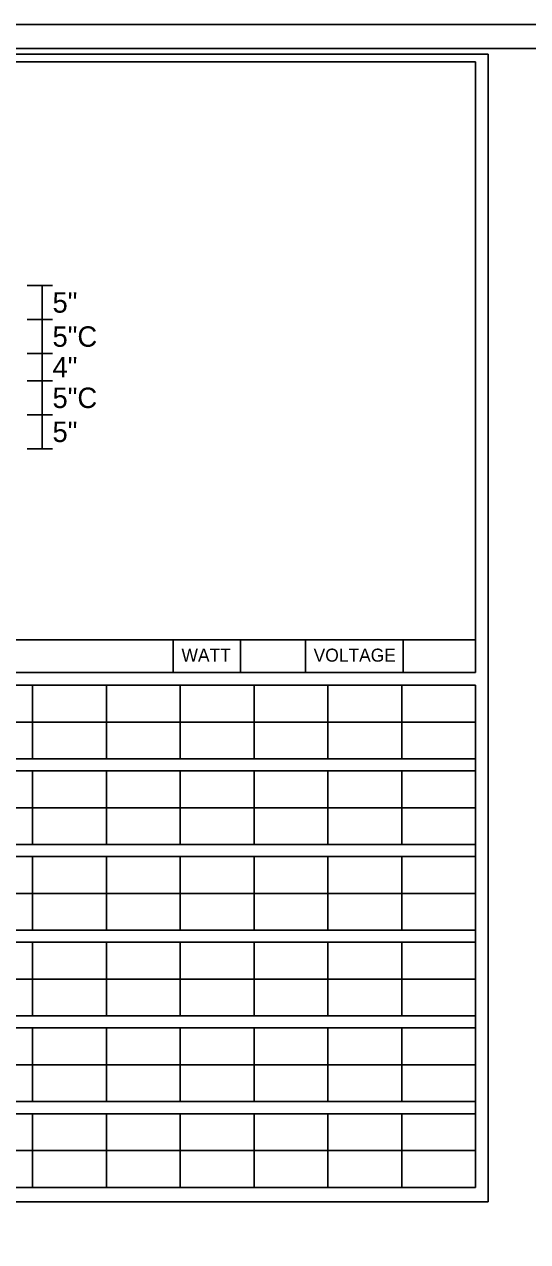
# Model space of a CAD drawing. Extents: x 17890587 to 17890754, y 17897693 to 17897992.
# Drawn here: x 17890605.35 to 17890611.5, y 17897889.3 to 17897904.2 of the extents above; entities that cross this region are included whole.
import ezdxf

# ---------------------------------------------------------------- set-up
doc = ezdxf.new("R2010")
doc.units = 0
for name, color, linetype in [('GSDims', 7, 'Continuous'), ('PlotBorder_dp', 7, 'Continuous'), ('SheetBorder_dp', 7, 'Continuous'), ('SheetLinesMisc2_dp', 7, 'Continuous'), ('TextMinor', 7, 'Continuous')]:
    doc.layers.add(name, color=color, linetype=linetype)

msp = doc.modelspace()

# ---------------------------------------------------------------- linework, layer by layer
at = {"layer": 'GSDims'}
for p, q in [((17890605.379, 17897901.007), (17890605.691, 17897901.007)), ((17890605.566, 17897900.591), (17890605.566, 17897901.007)), ((17890605.379, 17897900.591), (17890605.691, 17897900.591)), ((17890605.379, 17897900.591), (17890605.691, 17897900.591)), ((17890605.566, 17897900.591), (17890605.566, 17897900.174)), ((17890605.379, 17897900.174), (17890605.691, 17897900.174)), ((17890605.379, 17897900.174), (17890605.691, 17897900.174)), ((17890605.566, 17897899.841), (17890605.566, 17897900.174)), ((17890605.379, 17897899.841), (17890605.691, 17897899.841)), ((17890605.379, 17897899.841), (17890605.691, 17897899.841)), ((17890605.566, 17897899.841), (17890605.566, 17897899.424)), ((17890605.379, 17897899.424), (17890605.691, 17897899.424)), ((17890605.379, 17897899.424), (17890605.691, 17897899.424)), ((17890605.566, 17897899.007), (17890605.566, 17897899.424)), ((17890605.379, 17897899.007), (17890605.691, 17897899.007))]:
    msp.add_line(p, q, dxfattribs=at)
at = {"layer": 'PlotBorder_dp'}
msp.add_lwpolyline([(17890586.756, 17897873.104), (17890635.165, 17897873.104), (17890635.165, 17897904.203), (17890586.756, 17897904.203)], close=True, dxfattribs=at)
at = {"layer": 'SheetBorder_dp'}
msp.add_line((17890588.37, 17897903.909), (17890633.551, 17897903.909), dxfattribs=at)
at = {"layer": 'SheetLinesMisc2_dp'}
for p, q in [((17890588.454, 17897903.839), (17890611.019, 17897903.839)), ((17890611.019, 17897903.839), (17890611.019, 17897889.792)), ((17890595.516, 17897903.746), (17890610.866, 17897903.746)), ((17890610.866, 17897896.269), (17890610.866, 17897903.746)), ((17890595.516, 17897896.67), (17890610.866, 17897896.67)), ((17890607.167, 17897896.67), (17890607.167, 17897896.269)), ((17890607.99, 17897896.67), (17890607.99, 17897896.269)), ((17890608.784, 17897896.67), (17890608.784, 17897896.269)), ((17890609.98, 17897896.67), (17890609.98, 17897896.269)), ((17890595.516, 17897896.269), (17890610.866, 17897896.269)), ((17890588.67, 17897896.115), (17890610.866, 17897896.115)), ((17890605.448, 17897896.115), (17890605.448, 17897895.213)), ((17890606.351, 17897896.115), (17890606.351, 17897895.213)), ((17890607.254, 17897896.115), (17890607.254, 17897895.213)), ((17890608.157, 17897896.115), (17890608.157, 17897895.213)), ((17890609.06, 17897896.115), (17890609.06, 17897895.213)), ((17890609.963, 17897896.115), (17890609.963, 17897895.213)), ((17890610.866, 17897889.969), (17890610.866, 17897896.115)), ((17890588.67, 17897895.664), (17890610.866, 17897895.664)), ((17890588.67, 17897895.213), (17890610.866, 17897895.213)), ((17890588.67, 17897895.066), (17890610.866, 17897895.066)), ((17890605.448, 17897895.066), (17890605.448, 17897894.164)), ((17890606.351, 17897895.066), (17890606.351, 17897894.164)), ((17890607.254, 17897895.066), (17890607.254, 17897894.164)), ((17890608.157, 17897895.066), (17890608.157, 17897894.164)), ((17890609.06, 17897895.066), (17890609.06, 17897894.164)), ((17890609.963, 17897895.066), (17890609.963, 17897894.164)), ((17890588.67, 17897894.615), (17890610.866, 17897894.615)), ((17890588.67, 17897894.164), (17890610.866, 17897894.164)), ((17890588.67, 17897894.017), (17890610.866, 17897894.017)), ((17890605.448, 17897894.017), (17890605.448, 17897893.116)), ((17890606.351, 17897894.017), (17890606.351, 17897893.116)), ((17890607.254, 17897894.017), (17890607.254, 17897893.116)), ((17890608.157, 17897894.017), (17890608.157, 17897893.116)), ((17890609.06, 17897894.017), (17890609.06, 17897893.116)), ((17890609.963, 17897894.017), (17890609.963, 17897893.116)), ((17890588.67, 17897893.566), (17890610.866, 17897893.566)), ((17890588.67, 17897893.116), (17890610.866, 17897893.116)), ((17890588.67, 17897892.969), (17890610.866, 17897892.969)), ((17890605.448, 17897892.969), (17890605.448, 17897892.067)), ((17890606.351, 17897892.969), (17890606.351, 17897892.067)), ((17890607.254, 17897892.969), (17890607.254, 17897892.067)), ((17890608.157, 17897892.969), (17890608.157, 17897892.067)), ((17890609.06, 17897892.969), (17890609.06, 17897892.067)), ((17890609.963, 17897892.969), (17890609.963, 17897892.067)), ((17890588.67, 17897892.518), (17890610.866, 17897892.518)), ((17890588.67, 17897892.067), (17890610.866, 17897892.067)), ((17890588.67, 17897891.92), (17890610.866, 17897891.92)), ((17890605.448, 17897891.92), (17890605.448, 17897891.018)), ((17890606.351, 17897891.92), (17890606.351, 17897891.018)), ((17890607.254, 17897891.92), (17890607.254, 17897891.018)), ((17890608.157, 17897891.92), (17890608.157, 17897891.018)), ((17890609.06, 17897891.92), (17890609.06, 17897891.018)), ((17890609.963, 17897891.92), (17890609.963, 17897891.018)), ((17890588.67, 17897891.469), (17890610.866, 17897891.469)), ((17890588.67, 17897891.018), (17890610.866, 17897891.018)), ((17890588.67, 17897890.871), (17890610.866, 17897890.871)), ((17890605.448, 17897890.871), (17890605.448, 17897889.969)), ((17890606.351, 17897890.871), (17890606.351, 17897889.969)), ((17890607.254, 17897890.871), (17890607.254, 17897889.969)), ((17890608.157, 17897890.871), (17890608.157, 17897889.969)), ((17890609.06, 17897890.871), (17890609.06, 17897889.969)), ((17890609.963, 17897890.871), (17890609.963, 17897889.969)), ((17890588.67, 17897890.42), (17890610.866, 17897890.42)), ((17890588.67, 17897889.969), (17890610.866, 17897889.969)), ((17890588.454, 17897889.792), (17890611.019, 17897889.792))]:
    msp.add_line(p, q, dxfattribs=at)

# ---------------------------------------------------------------- texts
at = {"layer": 'GSDims'}
for s, p in [('5"', (17890605.691, 17897900.674)), ('5"C', (17890605.691, 17897900.257)), ('4"', (17890605.691, 17897899.882)), ('5"C', (17890605.691, 17897899.507)), ('5"', (17890605.691, 17897899.091))]:
    msp.add_text(s, height=0.25, dxfattribs=at).set_placement(p)
at = {"layer": 'TextMinor'}
for s, p in [('WATT', (17890607.269, 17897896.403)), ('VOLTAGE', (17890608.885, 17897896.403))]:
    msp.add_text(s, height=0.1594, dxfattribs=at).set_placement(p)

doc.saveas('drawing.dxf')
